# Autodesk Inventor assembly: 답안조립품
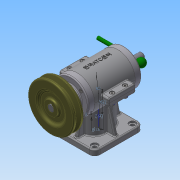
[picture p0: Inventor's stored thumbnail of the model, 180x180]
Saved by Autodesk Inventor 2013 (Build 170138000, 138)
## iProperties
Created: 2015-12
Part Number: 답안조립품
Document SubType Name: Assembly
Designer: Administrator
Author: Administrator
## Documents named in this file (19)
- C:\Users\Administrator\Desktop\351208V1036\답안조립품.iam
- C:\Users\Administrator\Desktop\351208V1036\본체.ipt
- C:\Users\Administrator\Desktop\351208V1036\V-벨트풀리.ipt
- C:\Users\Administrator\Desktop\351208V1036\너트 M4.ipt
- C:\Users\Administrator\Desktop\351208V1036\뒤커버.ipt
- C:\Users\Administrator\Desktop\351208V1036\레바.ipt
- C:\Users\Administrator\Desktop\351208V1036\멈춤나사 M3x8.ipt
- C:\Users\Administrator\Desktop\351208V1036\베어링 6201.ipt
- C:\Users\Administrator\Desktop\351208V1036\베어링 6202.ipt
- C:\Users\Administrator\Desktop\351208V1036\본체커버.ipt
- C:\Users\Administrator\Desktop\351208V1036\볼트 M3x0.5x8.ipt
- C:\Users\Administrator\Desktop\351208V1036\볼트 M4 x 16.ipt
- C:\Users\Administrator\Desktop\351208V1036\스프링.ipt
- C:\Users\Administrator\Desktop\351208V1036\슬라이드.ipt
- C:\Users\Administrator\Desktop\351208V1036\앞커버.ipt
- C:\Users\Administrator\Desktop\351208V1036\오일실 12 22 7.ipt
- C:\Users\Administrator\Desktop\351208V1036\와셔 ST 4-100.ipt
- C:\Users\Administrator\Desktop\351208V1036\키 4 x 4 x 18.ipt
- C:\Users\Administrator\Desktop\351208V1036\편심축.ipt
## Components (13 placed, 4 different names)
1. V-벨트풀리:1 — 플러쉬:1, 각도:1
2. ISO 4032 M4:1
3. ISO 4762 M4 x 16:1
4. ISO 7091 ST 4 - 100 HV:1
5. ISO 4762 M4 x 16:2
6. ISO 4762 M4 x 16:3
7. ISO 4762 M4 x 16:4
8. ISO 4032 M4:2
9. ISO 7091 ST 4 - 100 HV:2
10. ISO 4032 M4:3
11. ISO 7091 ST 4 - 100 HV:3
12. ISO 4032 M4:4
13. ISO 7091 ST 4 - 100 HV:4
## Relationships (2: Flush 1, Angle 1)
- 플러쉬:1 [Flush]: V-벨트풀리:1
- 각도:1 [Angle]: V-벨트풀리:1
